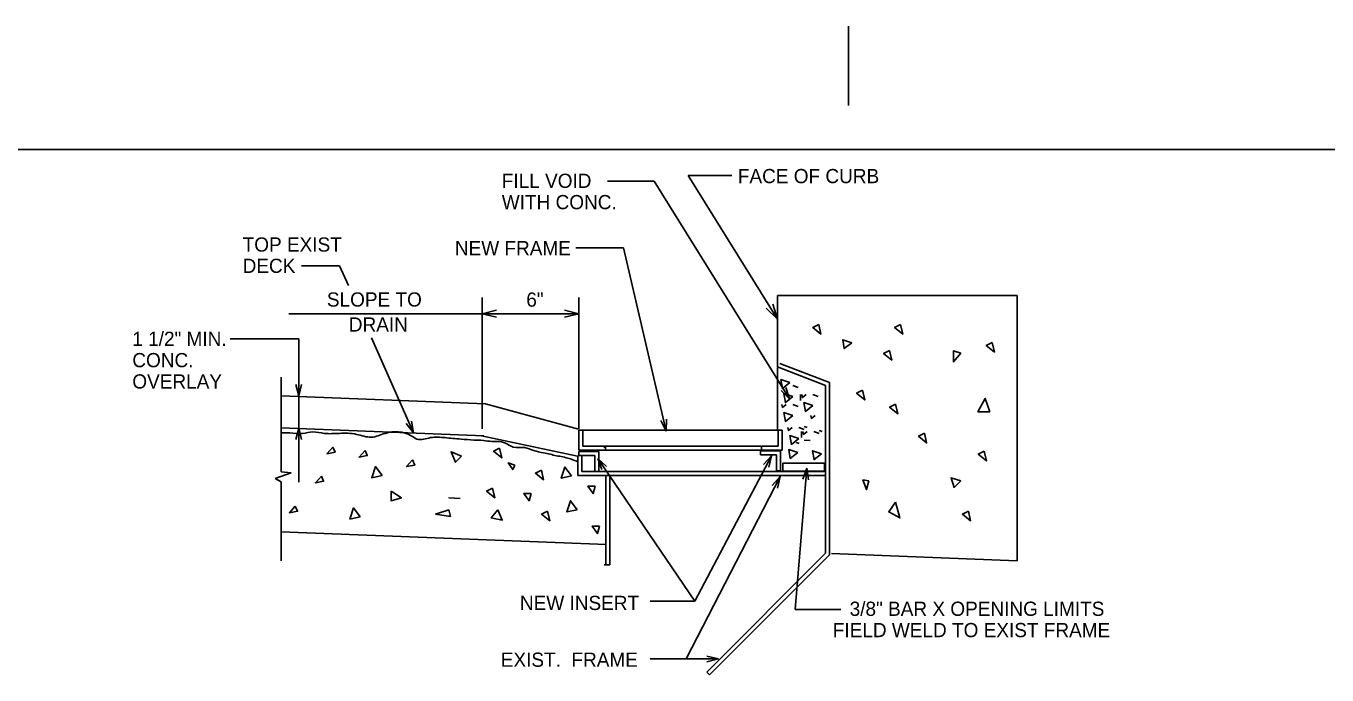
# Model space of a CAD drawing. Extents: x 973.2 to 1069.7, y 1484.4 to 1549.5.
# Drawn here: x 1004.28 to 1034.82, y 1532.03 to 1547.26 of the extents above; entities that cross this region are included whole.
import ezdxf

# ---------------------------------------------------------------- set-up
doc = ezdxf.new("R2010")
doc.units = 0
for name, color, linetype in [('Level 1', 7, 'Continuous'), ('Level 2', 7, 'Continuous'), ('Level 37', 7, 'Continuous')]:
    doc.layers.add(name, color=color, linetype=linetype)

msp = doc.modelspace()

# ---------------------------------------------------------------- linework, layer by layer
at = {"layer": 'Level 1'}
msp.add_line((1065.368, 1544.364), (981.8, 1544.364), dxfattribs=at)
at = {"layer": 'Level 2'}
for p, q in [((1019.024, 1543.621), (1017.923, 1543.621)), ((1019.024, 1543.621), (1022.201, 1538.516)), ((1019.822, 1543.755), (1021.921, 1540.383)), ((1020.847, 1543.755), (1019.822, 1543.755)), ((1017.186, 1542.06), (1018.3, 1542.06)), ((1018.3, 1542.06), (1019.303, 1537.758)), ((1010.744, 1541.637), (1011.638, 1541.637)), ((1011.638, 1541.637), (1011.844, 1541.173)), ((1014.983, 1540.893), (1014.983, 1537.81)), ((1017.251, 1540.893), (1017.251, 1537.81)), ((1021.921, 1539.262), (1021.921, 1540.935)), ((1021.921, 1540.935), (1027.546, 1540.935)), ((1027.546, 1540.935), (1027.546, 1534.71)), ((1014.983, 1540.632), (1014.983, 1540.699)), ((1017.251, 1540.676), (1017.251, 1540.699)), ((1021.921, 1540.383), (1021.654, 1540.641)), ((1021.921, 1540.383), (1021.807, 1540.736)), ((1010.442, 1540.511), (1017.251, 1540.511)), ((1010.677, 1539.921), (1009.065, 1539.921)), ((1010.677, 1538.583), (1010.677, 1539.921)), ((1012.387, 1539.945), (1013.374, 1537.714)), ((1023.14, 1538.893), (1021.97, 1539.343)), ((1023.046, 1538.829), (1021.921, 1539.262)), ((1021.921, 1537.794), (1021.921, 1539.252)), ((1010.264, 1536.8), (1010.264, 1539.018)), ((1010.677, 1538.583), (1010.609, 1538.853)), ((1010.677, 1538.583), (1010.744, 1538.853)), ((1022.201, 1538.516), (1022.116, 1538.781)), ((1022.402, 1538.776), (1022.277, 1538.824)), ((1023.046, 1537.14), (1023.046, 1538.829)), ((1023.14, 1538.893), (1023.14, 1534.851)), ((1015.064, 1538.394), (1010.264, 1538.585)), ((1010.677, 1537.826), (1010.677, 1538.583)), ((1022.201, 1538.516), (1022.002, 1538.71)), ((1022.46, 1538.473), (1022.46, 1538.613)), ((1022.871, 1538.565), (1022.745, 1538.613)), ((1017.244, 1537.802), (1015.064, 1538.394)), ((1022.402, 1538.331), (1022.277, 1538.379)), ((1015.021, 1537.646), (1010.264, 1537.834)), ((1010.677, 1537.826), (1010.609, 1537.556)), ((1010.677, 1536.555), (1010.677, 1537.826)), ((1010.677, 1537.826), (1010.744, 1537.556)), ((1013.374, 1537.714), (1013.203, 1537.934)), ((1013.374, 1537.714), (1013.326, 1537.988)), ((1019.303, 1537.758), (1019.176, 1538.006)), ((1019.303, 1537.758), (1019.308, 1538.037)), ((1022.543, 1537.792), (1022.417, 1537.841)), ((1022.613, 1537.839), (1022.543, 1537.867)), ((1017.22, 1537.166), (1014.97, 1537.647)), ((1017.251, 1537.78), (1017.251, 1537.311)), ((1022.024, 1537.78), (1017.251, 1537.78)), ((1017.345, 1537.78), (1017.345, 1537.405)), ((1021.93, 1537.791), (1021.93, 1537.405)), ((1022.024, 1537.78), (1022.024, 1537.311)), ((1022.483, 1537.607), (1022.483, 1537.747)), ((1022.684, 1537.536), (1022.543, 1537.542)), ((1022.894, 1537.699), (1022.768, 1537.747)), ((1022.965, 1537.746), (1022.894, 1537.773)), ((1022.024, 1537.311), (1017.251, 1537.311)), ((1017.253, 1537.278), (1017.253, 1537.184)), ((1017.253, 1537.278), (1017.727, 1537.278)), ((1021.535, 1537.405), (1017.345, 1537.405)), ((1017.721, 1537.278), (1017.721, 1536.809)), ((1017.859, 1537.419), (1017.859, 1537.364)), ((1017.877, 1537.408), (1017.877, 1537.309)), ((1021.519, 1537.294), (1021.519, 1537.2)), ((1021.519, 1537.294), (1021.988, 1537.294)), ((1021.539, 1537.401), (1021.539, 1537.325)), ((1021.93, 1537.405), (1021.546, 1537.405)), ((1021.988, 1537.294), (1021.988, 1536.825)), ((1022.426, 1537.465), (1022.356, 1537.492)), ((1017.233, 1537.181), (1017.233, 1536.712)), ((1017.253, 1537.184), (1017.628, 1537.184)), ((1017.327, 1537.166), (1017.327, 1536.806)), ((1017.628, 1536.809), (1017.628, 1537.184)), ((1017.698, 1537.112), (1019.975, 1533.768)), ((1017.698, 1537.112), (1017.906, 1536.927)), ((1017.698, 1537.112), (1017.794, 1536.851)), ((1019.975, 1533.768), (1021.778, 1537.179)), ((1021.519, 1537.2), (1021.894, 1537.2)), ((1021.778, 1537.179), (1021.592, 1536.972)), ((1021.778, 1537.179), (1021.711, 1536.908)), ((1021.894, 1536.825), (1021.894, 1537.2)), ((1022.045, 1537.001), (1023.018, 1537.001)), ((1022.045, 1536.814), (1022.045, 1537.001)), ((1023.018, 1536.814), (1023.018, 1537.001)), ((1023.046, 1537.14), (1023.046, 1534.89)), ((1010.125, 1536.641), (1010.503, 1536.78)), ((1010.264, 1536.568), (1010.125, 1536.641)), ((1010.503, 1536.78), (1010.264, 1536.8)), ((1023.019, 1536.712), (1017.233, 1536.712)), ((1023.014, 1536.806), (1017.327, 1536.806)), ((1017.628, 1536.809), (1017.749, 1536.809)), ((1017.89, 1536.712), (1017.89, 1534.62)), ((1017.983, 1536.712), (1017.983, 1534.62)), ((1019.772, 1532.409), (1021.978, 1536.689)), ((1021.978, 1536.689), (1021.795, 1536.48)), ((1021.894, 1536.825), (1021.988, 1536.825)), ((1021.978, 1536.689), (1021.915, 1536.418)), ((1022.045, 1536.814), (1023.018, 1536.814)), ((1022.335, 1533.568), (1022.603, 1536.889)), ((1022.603, 1536.889), (1022.514, 1536.626)), ((1022.603, 1536.889), (1022.648, 1536.615)), ((1010.264, 1534.708), (1010.264, 1536.568)), ((1017.906, 1535.092), (1010.264, 1535.394)), ((1023.046, 1534.89), (1020.256, 1532.1)), ((1023.14, 1534.851), (1020.322, 1532.034)), ((1027.546, 1534.71), (1023.188, 1534.883)), ((1017.983, 1534.62), (1017.851, 1534.62)), ((1017.89, 1534.62), (1017.98, 1534.62)), ((1017.983, 1534.62), (1017.98, 1534.62)), ((1018.925, 1533.768), (1019.975, 1533.768)), ((1023.405, 1533.568), (1022.335, 1533.568)), ((1018.925, 1532.409), (1020.531, 1532.409)), ((1020.531, 1532.409), (1020.261, 1532.476)), ((1020.531, 1532.409), (1020.261, 1532.341)), ((1020.256, 1532.1), (1020.323, 1532.033))]:
    msp.add_line(p, q, dxfattribs=at)
for points in [[(1015.317, 1540.595), (1014.983, 1540.511), (1015.317, 1540.428)], [(1016.918, 1540.595), (1017.251, 1540.511), (1016.918, 1540.428)], [(1022.59, 1538.613), (1022.503, 1538.544), (1022.491, 1538.613)], [(1022.122, 1538.379), (1022.034, 1538.31), (1022.023, 1538.379)], [(1022.801, 1538.122), (1022.713, 1538.052), (1022.702, 1538.122)], [(1022.262, 1537.841), (1022.174, 1537.771), (1022.163, 1537.841)], [(1022.614, 1537.747), (1022.526, 1537.677), (1022.514, 1537.747)]]:
    msp.add_lwpolyline(points, dxfattribs=at)
for points in [[(1022.885, 1540.258), (1022.746, 1540.188), (1022.938, 1540.032)], [(1024.805, 1540.259), (1024.666, 1540.189), (1024.858, 1540.032)], [(1023.661, 1539.83), (1023.486, 1539.691), (1023.451, 1539.9)], [(1024.548, 1539.65), (1024.408, 1539.58), (1024.6, 1539.423)], [(1026.96, 1539.837), (1026.82, 1539.767), (1027.012, 1539.61)], [(1026.22, 1539.587), (1026.046, 1539.378), (1026.046, 1539.639)], [(1022.209, 1538.894), (1022.034, 1538.754), (1021.999, 1538.963)], [(1022.279, 1538.566), (1022.105, 1538.427), (1022.07, 1538.636)], [(1023.916, 1538.713), (1023.776, 1538.643), (1023.968, 1538.487)], [(1026.9, 1538.211), (1026.621, 1538.211), (1026.795, 1538.524)], [(1022.279, 1538.121), (1022.105, 1537.982), (1022.07, 1538.191)], [(1022.747, 1538.355), (1022.573, 1538.216), (1022.538, 1538.425)], [(1024.688, 1538.385), (1024.549, 1538.315), (1024.741, 1538.159)], [(1022.419, 1537.582), (1022.245, 1537.443), (1022.21, 1537.652)], [(1025.367, 1537.706), (1025.228, 1537.636), (1025.419, 1537.479)], [(1011.478, 1537.38), (1011.338, 1537.223), (1011.53, 1537.258)], [(1012.236, 1537.302), (1012.096, 1537.145), (1012.288, 1537.18)], [(1014.5, 1537.166), (1014.361, 1537.026), (1014.256, 1537.271)], [(1015.392, 1537.355), (1015.253, 1537.285), (1015.444, 1537.128)], [(1022.393, 1537.254), (1022.218, 1537.115), (1022.183, 1537.324)], [(1022.949, 1537.225), (1022.775, 1537.086), (1022.74, 1537.295)], [(1026.772, 1537.285), (1026.632, 1537.215), (1026.824, 1537.058)], [(1012.636, 1536.714), (1012.479, 1536.923), (1012.392, 1536.662)], [(1013.35, 1537.079), (1013.211, 1536.922), (1013.402, 1536.957)], [(1015.754, 1536.957), (1015.702, 1536.852), (1015.597, 1537.009)], [(1017.083, 1536.703), (1016.926, 1536.912), (1016.839, 1536.651)], [(1011.211, 1536.7), (1011.071, 1536.543), (1011.263, 1536.578)], [(1016.376, 1536.84), (1016.236, 1536.77), (1016.428, 1536.613)], [(1024.061, 1536.591), (1024.009, 1536.382), (1023.922, 1536.609)], [(1026.22, 1536.591), (1026.064, 1536.434), (1025.994, 1536.661)], [(1012.845, 1536.347), (1012.845, 1536.121), (1013.089, 1536.191)], [(1015.229, 1536.418), (1015.089, 1536.348), (1015.281, 1536.192)], [(1016.137, 1536.295), (1016.084, 1536.121), (1015.963, 1536.295)], [(1017.641, 1536.462), (1017.589, 1536.288), (1017.467, 1536.462)], [(1010.597, 1535.998), (1010.458, 1535.841), (1010.649, 1535.876)], [(1014.465, 1536.173), (1014.204, 1536.191)], [(1017.217, 1535.912), (1017.06, 1536.121), (1016.973, 1535.86)], [(1024.688, 1536.086), (1024.531, 1535.86), (1024.792, 1535.72)], [(1012.123, 1535.745), (1011.966, 1535.954), (1011.879, 1535.693)], [(1014.204, 1535.912), (1014.238, 1535.755), (1013.89, 1535.807)], [(1015.353, 1535.912), (1015.457, 1535.668), (1015.196, 1535.72)], [(1016.516, 1535.88), (1016.377, 1535.81), (1016.569, 1535.654)], [(1026.398, 1535.88), (1026.258, 1535.81), (1026.45, 1535.653)], [(1017.742, 1535.526), (1017.689, 1535.352), (1017.568, 1535.526)]]:
    msp.add_lwpolyline(points, close=True, dxfattribs=at)
msp.add_spline([(1017.23, 1537.034), (1017.029, 1537.112), (1016.729, 1537.179), (1016.428, 1537.245), (1016.194, 1537.301), (1015.982, 1537.368), (1015.714, 1537.379), (1015.581, 1537.446), (1015.391, 1537.513), (1015.213, 1537.513), (1015.012, 1537.535), (1014.789, 1537.547), (1014.488, 1537.569), (1014.109, 1537.602), (1013.775, 1537.602), (1013.452, 1537.569), (1013.318, 1537.647), (1012.705, 1537.703), (1012.382, 1537.613), (1012.036, 1537.68), (1011.635, 1537.703), (1011.278, 1537.703), (1011.011, 1537.736), (1010.766, 1537.703), (1010.465, 1537.714), (1010.275, 1537.714)], degree=3, dxfattribs=at)
at = {"layer": 'Level 37'}
msp.add_line((1023.584, 1545.397), (1023.584, 1547.262), dxfattribs=at)

# ---------------------------------------------------------------- texts
at = {"layer": 'Level 2'}
for s, height, p in [('FILL VOID', 0.3333, (1015.445, 1543.463)), ('FACE OF CURB', 0.33333, (1020.987, 1543.574)), ('WITH CONC.', 0.3333, (1015.445, 1542.963)), ('TOP EXIST', 0.3333, (1009.361, 1541.968)), ('NEW FRAME', 0.3333, (1014.344, 1541.884)), ('DECK', 0.3333, (1009.361, 1541.468)), ('SLOPE TO', 0.3333, (1011.339, 1540.678)), ('6"', 0.3333, (1016.02, 1540.676)), ('DRAIN', 0.3333, (1011.854, 1540.091)), ('1 1/2" MIN.', 0.33333, (1006.771, 1539.755)), ('CONC.  ', 0.3333, (1006.771, 1539.255)), ('OVERLAY', 0.3333, (1006.771, 1538.755)), ('NEW INSERT', 0.3333, (1015.871, 1533.557)), ('3/8" BAR X OPENING LIMITS', 0.33333, (1023.612, 1533.42)), ('FIELD WELD TO EXIST FRAME', 0.33333, (1023.216, 1532.92)), ('EXIST.  FRAME', 0.33333, (1015.421, 1532.225))]:
    msp.add_text(s, height=height, dxfattribs=at).set_placement(p)

doc.saveas('drawing.dxf')
